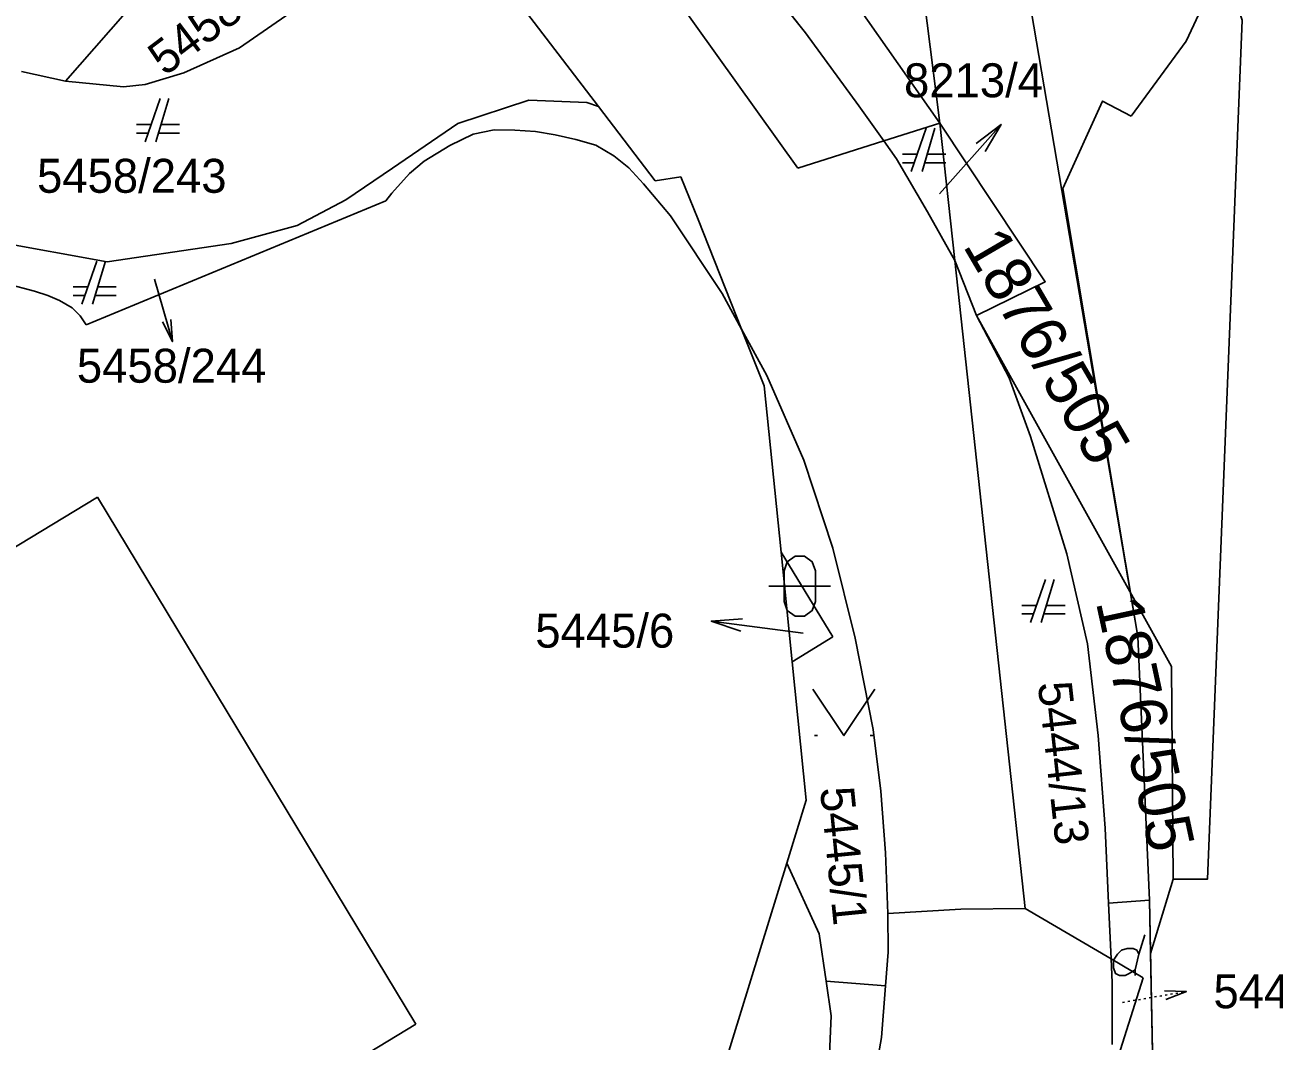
# Model space of a CAD drawing. Extents: x -263587 to -261993, y -1238795 to -1236748.
# Drawn here: x -262782.82 to -262742.4, y -1237272.29 to -1237239.39 of the extents above; entities that cross this region are included whole.
import ezdxf

# ---------------------------------------------------------------- set-up
doc = ezdxf.new("R2010")
doc.units = 0
for name, color, linetype in [('Vrstva 1', 7, 'Continuous'), ('Vrstva 2', 7, 'Continuous'), ('Vrstva 3', 7, 'Continuous')]:
    doc.layers.add(name, color=color, linetype=linetype)

msp = doc.modelspace()

# ---------------------------------------------------------------- linework, layer by layer
at = {"layer": 'Vrstva 1'}
for p, q in [((-262746.8, -1237259.19), (-262759.37, -1237185.43)), ((-262759.37, -1237185.43), (-262746.8, -1237259.19)), ((-262760.4, -1237185.76), (-262753.21, -1237242.57)), ((-262790.98, -1237197.67), (-262757.81, -1237244.02)), ((-262757.81, -1237244.02), (-262790.98, -1237197.67)), ((-262764.26, -1237242.03), (-262771.48, -1237232.59)), ((-262771.48, -1237232.59), (-262764.26, -1237242.03)), ((-262763.18, -1237232.58), (-262757.56, -1237239.64)), ((-262757.56, -1237239.64), (-262763.18, -1237232.58)), ((-262777.13, -1237236.2), (-262781.51, -1237241.21)), ((-262781.51, -1237241.21), (-262777.13, -1237236.2)), ((-262773.93, -1237238.78), (-262775.88, -1237240.13)), ((-262775.88, -1237240.13), (-262773.93, -1237238.78)), ((-262757.56, -1237239.64), (-262755.84, -1237242)), ((-262755.84, -1237242), (-262757.56, -1237239.64)), ((-262775.88, -1237240.13), (-262777.68, -1237240.93)), ((-262777.68, -1237240.93), (-262775.88, -1237240.13)), ((-262781.51, -1237241.21), (-262782.94, -1237240.89)), ((-262782.94, -1237240.89), (-262781.51, -1237241.21)), ((-262777.68, -1237240.93), (-262778.94, -1237241.31)), ((-262778.94, -1237241.31), (-262777.68, -1237240.93)), ((-262779.64, -1237241.39), (-262781.51, -1237241.21)), ((-262781.51, -1237241.21), (-262779.64, -1237241.39)), ((-262778.94, -1237241.31), (-262779.64, -1237241.39)), ((-262779.64, -1237241.39), (-262778.94, -1237241.31)), ((-262778.45, -1237241.77), (-262778.94, -1237243.17)), ((-262778.59, -1237243.17), (-262778.17, -1237241.77)), ((-262768.81, -1237242.58), (-262766.52, -1237241.82)), ((-262766.52, -1237241.82), (-262768.81, -1237242.58)), ((-262766.52, -1237241.82), (-262764.64, -1237241.9)), ((-262764.64, -1237241.9), (-262766.52, -1237241.82)), ((-262764.64, -1237241.9), (-262764.26, -1237242.03)), ((-262764.26, -1237242.03), (-262764.64, -1237241.9)), ((-262762.43, -1237244.43), (-262764.26, -1237242.03)), ((-262764.26, -1237242.03), (-262762.43, -1237244.43)), ((-262755.84, -1237242), (-262755.03, -1237243.14)), ((-262755.03, -1237243.14), (-262755.84, -1237242)), ((-262770.93, -1237244.02), (-262768.81, -1237242.58)), ((-262768.81, -1237242.58), (-262770.93, -1237244.02)), ((-262755.03, -1237243.14), (-262753.21, -1237242.57)), ((-262753.21, -1237242.57), (-262755.03, -1237243.14)), ((-262753.21, -1237242.57), (-262752.73, -1237247.01)), ((-262752.73, -1237247.01), (-262753.21, -1237242.57)), ((-262778.744, -1237242.61), (-262779.22, -1237242.61)), ((-262779.22, -1237242.89), (-262778.842, -1237242.89)), ((-262778.506, -1237242.89), (-262777.82, -1237242.89)), ((-262777.82, -1237242.61), (-262778.422, -1237242.61)), ((-262768.32, -1237242.92), (-262769.07, -1237243.29)), ((-262769.07, -1237243.29), (-262768.32, -1237242.92)), ((-262767.64, -1237242.78), (-262768.32, -1237242.92)), ((-262768.32, -1237242.92), (-262767.64, -1237242.78)), ((-262766.97, -1237242.79), (-262767.64, -1237242.78)), ((-262767.64, -1237242.78), (-262766.97, -1237242.79)), ((-262766.3, -1237242.84), (-262766.97, -1237242.79)), ((-262766.97, -1237242.79), (-262766.3, -1237242.84)), ((-262765.66, -1237242.94), (-262766.3, -1237242.84)), ((-262766.3, -1237242.84), (-262765.66, -1237242.94)), ((-262765, -1237243.09), (-262765.66, -1237242.94)), ((-262765.66, -1237242.94), (-262765, -1237243.09)), ((-262753.65, -1237242.73), (-262754.14, -1237244.13)), ((-262753.79, -1237244.13), (-262753.37, -1237242.73)), ((-262752.041, -1237243.222), (-262751.228, -1237242.607)), ((-262769.07, -1237243.29), (-262769.9, -1237243.8)), ((-262769.9, -1237243.8), (-262769.07, -1237243.29)), ((-262764.35, -1237243.28), (-262765, -1237243.09)), ((-262765, -1237243.09), (-262764.35, -1237243.28)), ((-262763.77, -1237243.62), (-262764.35, -1237243.28)), ((-262764.35, -1237243.28), (-262763.77, -1237243.62)), ((-262757.81, -1237244.02), (-262755.03, -1237243.14)), ((-262755.03, -1237243.14), (-262757.81, -1237244.02)), ((-262755.03, -1237243.14), (-262754.62, -1237243.72)), ((-262754.62, -1237243.72), (-262755.03, -1237243.14)), ((-262763.28, -1237244.01), (-262763.77, -1237243.62)), ((-262763.77, -1237243.62), (-262763.28, -1237244.01)), ((-262754.62, -1237243.72), (-262753.61, -1237245.44)), ((-262753.61, -1237245.44), (-262754.62, -1237243.72)), ((-262753.944, -1237243.57), (-262754.42, -1237243.57)), ((-262753.02, -1237243.57), (-262753.622, -1237243.57)), ((-262772.44, -1237245.05), (-262770.93, -1237244.02)), ((-262770.93, -1237244.02), (-262772.44, -1237245.05)), ((-262770.38, -1237244.2), (-262770.95, -1237244.83)), ((-262770.95, -1237244.83), (-262770.38, -1237244.2)), ((-262769.9, -1237243.8), (-262770.38, -1237244.2)), ((-262770.38, -1237244.2), (-262769.9, -1237243.8)), ((-262762.81, -1237244.53), (-262763.28, -1237244.01)), ((-262763.28, -1237244.01), (-262762.81, -1237244.53)), ((-262754.42, -1237243.85), (-262754.042, -1237243.85)), ((-262753.706, -1237243.85), (-262753.02, -1237243.85)), ((-262761.93, -1237245.57), (-262762.81, -1237244.53)), ((-262762.81, -1237244.53), (-262761.93, -1237245.57)), ((-262761.6, -1237244.3), (-262762.43, -1237244.43)), ((-262762.43, -1237244.43), (-262761.6, -1237244.3)), ((-262761.04, -1237245.69), (-262761.6, -1237244.3)), ((-262761.6, -1237244.3), (-262761.04, -1237245.69)), ((-262770.95, -1237244.83), (-262771.14, -1237245.08)), ((-262771.14, -1237245.08), (-262770.95, -1237244.83)), ((-262771.14, -1237245.08), (-262780.84, -1237249.1)), ((-262780.84, -1237249.1), (-262771.14, -1237245.08)), ((-262774.01, -1237245.88), (-262772.44, -1237245.05)), ((-262772.44, -1237245.05), (-262774.01, -1237245.88)), ((-262760.26, -1237248.08), (-262761.93, -1237245.57)), ((-262761.93, -1237245.57), (-262760.26, -1237248.08)), ((-262759.63, -1237249.24), (-262761.04, -1237245.69)), ((-262761.04, -1237245.69), (-262759.63, -1237249.24)), ((-262753.61, -1237245.44), (-262752.73, -1237247.01)), ((-262752.73, -1237247.01), (-262753.61, -1237245.44)), ((-262784.77, -1237246.22), (-262780.16, -1237247.06)), ((-262780.16, -1237247.06), (-262784.77, -1237246.22)), ((-262776.15, -1237246.46), (-262774.01, -1237245.88)), ((-262774.01, -1237245.88), (-262776.15, -1237246.46)), ((-262780.16, -1237247.06), (-262776.15, -1237246.46)), ((-262776.15, -1237246.46), (-262780.16, -1237247.06)), ((-262780.5, -1237247.03), (-262780.99, -1237248.43)), ((-262780.64, -1237248.43), (-262780.22, -1237247.03)), ((-262752.73, -1237247.01), (-262750.45, -1237268)), ((-262750.45, -1237268), (-262752.73, -1237247.01)), ((-262752.73, -1237247.01), (-262752.03, -1237248.79)), ((-262752.03, -1237248.79), (-262752.73, -1237247.01)), ((-262782.52, -1237248.01), (-262783.41, -1237247.77)), ((-262783.41, -1237247.77), (-262782.52, -1237248.01)), ((-262782.08, -1237248.15), (-262782.52, -1237248.01)), ((-262782.52, -1237248.01), (-262782.08, -1237248.15)), ((-262781.71, -1237248.31), (-262782.08, -1237248.15)), ((-262782.08, -1237248.15), (-262781.71, -1237248.31)), ((-262780.794, -1237247.87), (-262781.27, -1237247.87)), ((-262781.27, -1237248.15), (-262780.892, -1237248.15)), ((-262780.556, -1237248.15), (-262779.87, -1237248.15)), ((-262779.87, -1237247.87), (-262780.472, -1237247.87)), ((-262759.63, -1237249.24), (-262760.26, -1237248.08)), ((-262760.26, -1237248.08), (-262759.63, -1237249.24)), ((-262781.3, -1237248.55), (-262781.71, -1237248.31)), ((-262781.71, -1237248.31), (-262781.3, -1237248.55)), ((-262781.04, -1237248.8), (-262781.3, -1237248.55)), ((-262781.3, -1237248.55), (-262781.04, -1237248.8)), ((-262780.84, -1237249.1), (-262781.04, -1237248.8)), ((-262781.04, -1237248.8), (-262780.84, -1237249.1)), ((-262778.109, -1237248.927), (-262778.051, -1237249.639)), ((-262752.03, -1237248.79), (-262750.97, -1237250.81)), ((-262750.97, -1237250.81), (-262752.03, -1237248.79)), ((-262758.81, -1237250.74), (-262759.63, -1237249.24)), ((-262758.9, -1237251.07), (-262759.63, -1237249.24)), ((-262759.63, -1237249.24), (-262758.81, -1237250.74)), ((-262759.63, -1237249.24), (-262758.9, -1237251.07)), ((-262758.35, -1237256.46), (-262758.9, -1237251.07)), ((-262758.9, -1237251.07), (-262758.35, -1237256.46)), ((-262757.62, -1237253.48), (-262758.81, -1237250.74)), ((-262758.81, -1237250.74), (-262757.62, -1237253.48)), ((-262750.97, -1237250.81), (-262750.28, -1237252.71)), ((-262750.28, -1237252.71), (-262750.97, -1237250.81)), ((-262750.28, -1237252.71), (-262749.1, -1237256.51)), ((-262749.1, -1237256.51), (-262750.28, -1237252.71)), ((-262756.68, -1237256.33), (-262757.62, -1237253.48)), ((-262757.62, -1237253.48), (-262756.68, -1237256.33)), ((-262786.81, -1237258.51), (-262780.48, -1237254.68)), ((-262780.48, -1237254.68), (-262786.81, -1237258.51)), ((-262780.48, -1237254.68), (-262770.17, -1237271.74)), ((-262770.17, -1237271.74), (-262780.48, -1237254.68)), ((-262758.35, -1237256.46), (-262756.68, -1237259.2)), ((-262757.99, -1237260.01), (-262758.35, -1237256.46)), ((-262756.68, -1237259.2), (-262758.35, -1237256.46)), ((-262758.35, -1237256.46), (-262757.99, -1237260.01)), ((-262755.95, -1237259.24), (-262756.68, -1237256.33)), ((-262756.68, -1237256.33), (-262755.95, -1237259.24)), ((-262749.1, -1237256.51), (-262748.43, -1237259.43)), ((-262748.43, -1237259.43), (-262749.1, -1237256.51)), ((-262749.79, -1237257.34), (-262750.28, -1237258.74)), ((-262749.93, -1237258.74), (-262749.51, -1237257.34)), ((-262750.084, -1237258.18), (-262750.56, -1237258.18)), ((-262749.16, -1237258.18), (-262749.762, -1237258.18)), ((-262759.649, -1237259.017), (-262760.614, -1237258.689)), ((-262750.56, -1237258.46), (-262750.182, -1237258.46)), ((-262749.846, -1237258.46), (-262749.16, -1237258.46)), ((-262756.68, -1237259.2), (-262757.99, -1237260.01)), ((-262757.99, -1237260.01), (-262756.68, -1237259.2)), ((-262755.37, -1237262.2), (-262755.95, -1237259.24)), ((-262755.95, -1237259.24), (-262755.37, -1237262.2)), ((-262748.43, -1237259.43), (-262748.09, -1237262.4)), ((-262748.09, -1237262.4), (-262748.43, -1237259.43)), ((-262746.43, -1237267.73), (-262746.8, -1237259.19)), ((-262746.8, -1237259.19), (-262746.43, -1237267.73)), ((-262757.54, -1237264.49), (-262757.99, -1237260.01)), ((-262757.99, -1237260.01), (-262757.54, -1237264.49)), ((-262755.12, -1237264.2), (-262755.37, -1237262.2)), ((-262755.37, -1237262.2), (-262755.12, -1237264.2)), ((-262757.27, -1237262.4), (-262757.17, -1237262.4)), ((-262755.47, -1237262.4), (-262755.37, -1237262.4)), ((-262748.09, -1237262.4), (-262747.86, -1237265.4)), ((-262747.86, -1237265.4), (-262748.09, -1237262.4)), ((-262754.97, -1237266.2), (-262755.12, -1237264.2)), ((-262755.12, -1237264.2), (-262754.97, -1237266.2)), ((-262758.17, -1237266.53), (-262757.54, -1237264.49)), ((-262757.54, -1237264.49), (-262758.17, -1237266.53)), ((-262747.86, -1237265.4), (-262747.75, -1237267.82)), ((-262747.75, -1237267.82), (-262747.86, -1237265.4)), ((-262754.9, -1237268.16), (-262754.97, -1237266.2)), ((-262754.97, -1237266.2), (-262754.9, -1237268.16)), ((-262762.07, -1237279.22), (-262758.17, -1237266.53)), ((-262758.17, -1237266.53), (-262762.07, -1237279.22)), ((-262758.17, -1237266.53), (-262757.12, -1237268.82)), ((-262757.12, -1237268.82), (-262758.17, -1237266.53)), ((-262752.53, -1237268.02), (-262754.9, -1237268.16)), ((-262754.9, -1237268.16), (-262752.53, -1237268.02)), ((-262750.45, -1237268), (-262752.53, -1237268.02)), ((-262752.53, -1237268.02), (-262750.45, -1237268)), ((-262750.45, -1237268), (-262747.67, -1237269.63)), ((-262747.67, -1237269.63), (-262750.45, -1237268)), ((-262747.75, -1237267.82), (-262746.43, -1237267.73)), ((-262746.43, -1237267.73), (-262747.75, -1237267.82)), ((-262747.67, -1237269.63), (-262747.75, -1237267.82)), ((-262747.75, -1237267.82), (-262747.67, -1237269.63)), ((-262745.96, -1237291.09), (-262746.43, -1237267.73)), ((-262746.43, -1237267.73), (-262745.96, -1237291.09)), ((-262754.89, -1237269.41), (-262754.9, -1237268.16)), ((-262754.9, -1237268.16), (-262754.89, -1237269.41)), ((-262757.12, -1237268.82), (-262756.89, -1237270.35)), ((-262756.89, -1237270.35), (-262757.12, -1237268.82)), ((-262746.769, -1237269.477), (-262746.58, -1237268.847)), ((-262754.97, -1237270.5), (-262754.89, -1237269.41)), ((-262754.89, -1237269.41), (-262754.97, -1237270.5)), ((-262747.64, -1237270.39), (-262747.67, -1237269.63)), ((-262747.67, -1237269.63), (-262746.63, -1237270.24)), ((-262747.67, -1237269.63), (-262747.64, -1237270.39)), ((-262746.63, -1237270.24), (-262747.67, -1237269.63)), ((-262756.89, -1237270.35), (-262756.73, -1237271.47)), ((-262756.73, -1237271.47), (-262756.89, -1237270.35)), ((-262756.89, -1237270.35), (-262754.97, -1237270.5)), ((-262754.97, -1237270.5), (-262756.89, -1237270.35)), ((-262746.63, -1237270.24), (-262747.78, -1237273.87)), ((-262747.78, -1237273.87), (-262746.63, -1237270.24)), ((-262747.64, -1237272.4), (-262747.64, -1237270.39)), ((-262747.64, -1237270.39), (-262747.64, -1237272.4)), ((-262754.97, -1237270.5), (-262755.1, -1237272.18)), ((-262755.1, -1237272.18), (-262754.97, -1237270.5)), ((-262746.437, -1237270.893), (-262746.368, -1237270.881)), ((-262746.265, -1237270.864), (-262746.196, -1237270.852)), ((-262746.092, -1237270.834), (-262746.023, -1237270.823)), ((-262745.92, -1237270.805), (-262745.851, -1237270.793)), ((-262745.747, -1237270.776), (-262745.678, -1237270.764)), ((-262745.575, -1237270.746), (-262745.506, -1237270.735)), ((-262745.402, -1237270.717), (-262745.333, -1237270.705)), ((-262747.3, -1237271.04), (-262747.231, -1237271.028)), ((-262747.127, -1237271.011), (-262747.058, -1237270.999)), ((-262746.955, -1237270.981), (-262746.886, -1237270.97)), ((-262746.782, -1237270.952), (-262746.713, -1237270.94)), ((-262746.61, -1237270.923), (-262746.541, -1237270.911)), ((-262756.73, -1237271.47), (-262756.84, -1237274.15)), ((-262756.84, -1237274.15), (-262756.73, -1237271.47)), ((-262770.17, -1237271.74), (-262800.01, -1237289.78)), ((-262800.01, -1237289.78), (-262770.17, -1237271.74)), ((-262755.1, -1237272.18), (-262755.59, -1237274.83)), ((-262755.59, -1237274.83), (-262755.1, -1237272.18))]:
    msp.add_line(p, q, dxfattribs=at)
for points in [[(-262753.22, -1237244.85), (-262751.228, -1237242.607), (-262751.742, -1237243.487)], [(-262778.63, -1237247.62), (-262778.051, -1237249.639), (-262778.378, -1237249.004)], [(-262758.75, -1237257.56), (-262757.48, -1237257.56), (-262756.75, -1237257.56)], [(-262757.64, -1237259.08), (-262760.614, -1237258.689), (-262759.597, -1237258.621)], [(-262757.32, -1237260.9), (-262756.32, -1237262.4), (-262755.32, -1237260.9)], [(-262746.895, -1237270.17), (-262746.895, -1237269.981), (-262746.769, -1237269.477), (-262746.832, -1237269.351), (-262746.958, -1237269.288), (-262747.147, -1237269.288), (-262747.336, -1237269.351), (-262747.462, -1237269.477), (-262747.588, -1237269.666), (-262747.588, -1237269.918), (-262747.525, -1237270.107), (-262747.399, -1237270.17), (-262747.21, -1237270.17), (-262747.084, -1237270.107), (-262746.895, -1237269.981)], [(-262745.896, -1237270.943), (-262745.23, -1237270.688), (-262745.943, -1237270.667)]]:
    msp.add_lwpolyline(points, dxfattribs=at)
msp.add_lwpolyline([(-262758.25, -1237257.06), (-262758.15, -1237256.77), (-262757.9, -1237256.59), (-262757.59, -1237256.59), (-262757.34, -1237256.77), (-262757.24, -1237257.06), (-262757.24, -1237258.06), (-262757.34, -1237258.35), (-262757.59, -1237258.53), (-262757.9, -1237258.53), (-262758.15, -1237258.35), (-262758.25, -1237258.06)], close=True, dxfattribs=at)
at = {"layer": 'Vrstva 2'}
msp.add_line((-262747.015, -1237242.339), (-262745.24, -1237239.91), dxfattribs=at)
for points in [[(-262745.241, -1237239.91), (-262743.35, -1237235.87), (-262743.128, -1237231.498), (-262744.48, -1237227.373), (-262747.62, -1237224.23), (-262750.911, -1237222.518), (-262750.927, -1237222.08), (-262749.63, -1237222.22), (-262749.36, -1237220.44), (-262749.54, -1237220.17), (-262752.97, -1237217.86), (-262756.398, -1237215.55), (-262756.25, -1237215.1), (-262754.635, -1237213.215)], [(-262751.363, -1237345.612), (-262751.817, -1237337.772), (-262753.2, -1237330.37), (-262753.45, -1237319.94), (-262747.72, -1237316.528), (-262749.531, -1237313.687), (-262744.87, -1237310.88), (-262744.576, -1237308.121), (-262744.632, -1237307.727), (-262746.13, -1237308.63), (-262746.16, -1237306.31), (-262747.66, -1237292.16), (-262745.96, -1237291.09), (-262745.96, -1237291.09), (-262746.43, -1237267.73), (-262746.8, -1237259.19), (-262749.227, -1237244.683), (-262747.946, -1237241.849), (-262747.015, -1237242.339)]]:
    msp.add_lwpolyline(points, dxfattribs=at)
at = {"layer": 'Vrstva 3'}
for points in [[(-262748.29, -1237225.02), (-262743.43, -1237239.23), (-262744.55, -1237267.05), (-262745.66, -1237267.05), (-262745.71, -1237260.16), (-262752.03, -1237248.79), (-262749.8, -1237247.7), (-262753.21, -1237242.57), (-262774.08, -1237212.83), (-262787.389, -1237196.921), (-262783.74, -1237196.16), (-262769.952, -1237186.148), (-262759.86, -1237200.23), (-262749.81, -1237222.97)], [(-262787.389, -1237196.921), (-262774.08, -1237212.83), (-262753.21, -1237242.57), (-262755.03, -1237243.14), (-262755.84, -1237242), (-262757.56, -1237239.64), (-262763.18, -1237232.58), (-262767.47, -1237226.83), (-262774.92, -1237216.2), (-262779.31, -1237209.74), (-262784.97, -1237201.5), (-262788.04, -1237197.06)], [(-262753.21, -1237242.57), (-262749.8, -1237247.7), (-262752.03, -1237248.79), (-262752.73, -1237247.01)], [(-262752.03, -1237248.79), (-262745.71, -1237260.16), (-262745.66, -1237267.05), (-262746.395, -1237269.455), (-262746.43, -1237267.73), (-262747.75, -1237267.82), (-262747.86, -1237265.4), (-262748.09, -1237262.4), (-262748.43, -1237259.43), (-262749.1, -1237256.51), (-262750.28, -1237252.71), (-262750.97, -1237250.81)]]:
    msp.add_lwpolyline(points, close=True, dxfattribs=at)
msp.add_lwpolyline([(-262781.6, -1237646.81), (-262760.18, -1237607.41), (-262746.49, -1237565.17), (-262744.57, -1237538.03), (-262742.42, -1237509.51), (-262743.25, -1237500.01), (-262747.55, -1237499.97), (-262749.11, -1237476.18), (-262748.79, -1237440.91), (-262747.23, -1237375.51), (-262746.13, -1237308.63), (-262749.07, -1237311.22), (-262749.15, -1237308.17), (-262746.16, -1237306.31), (-262747.51, -1237293.89), (-262747.66, -1237292.16), (-262745.96, -1237291.09), (-262746.395, -1237269.455), (-262745.66, -1237267.05), (-262744.55, -1237267.05), (-262743.43, -1237239.23), (-262748.29, -1237225.02), (-262744.25, -1237230.5), (-262727.51, -1237252.7)], dxfattribs=at)

# ---------------------------------------------------------------- texts
at = {"layer": 'Vrstva 1'}
for s, rotation, p in [('5458/258', 37.185, (-262778.295, -1237241.062)), ('5444/13', 276.3375, (-262750.045, -1237260.7)), ('5445/1', 275.7073, (-262757.093, -1237264.105))]:
    msp.add_text(s, height=1.1, rotation=rotation, dxfattribs=at).set_placement(p)
for s, p in [('8213/4', (-262754.372, -1237241.727)), ('5458/243', (-262782.435, -1237244.82)), ('5458/244', (-262781.145, -1237250.97)), ('5445/6', (-262766.308, -1237259.55)), ('5447/29', (-262744.356, -1237271.23))]:
    msp.add_text(s, height=1.1, dxfattribs=at).set_placement(p)
at = {"layer": 'Vrstva 3'}
for rotation, p in [(300.2299, (-262752.486, -1237246.534)), (282.1244, (-262748.166, -1237258.075))]:
    msp.add_text('1876/505', height=1.5, rotation=rotation, dxfattribs=at).set_placement(p)

doc.saveas('drawing.dxf')
